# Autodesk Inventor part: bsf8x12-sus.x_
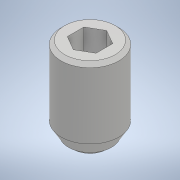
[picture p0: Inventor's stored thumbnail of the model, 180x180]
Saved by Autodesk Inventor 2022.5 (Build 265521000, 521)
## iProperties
Created: 2020-01
Part Number: bsf8x12-sus.x_
Material: 一般
Document SubType Name: Modeling
Designer: ImaoCorp
Density: 1 g/cm^3
Appearance: 既定
Sending System: SOLIDWORKS 2018-2018316
MC: AMD64
MC_MODEL: Intel64 Family 6 Model 60 Stepping 3, GenuineIntel
OS: Windows_NT
FRU: Parasolid Version 30.0, build 310,  6- 8-2018
FORMAT: text
GUISE: transmit
KEY: bsf8x12-sus
FILE: bsf8x12-sus.x_t
DATE: Thu Jan 23 16:48:22 2020
Author: ImaoCorp
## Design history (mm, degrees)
feature "Base1"
node "ソリッド1"
